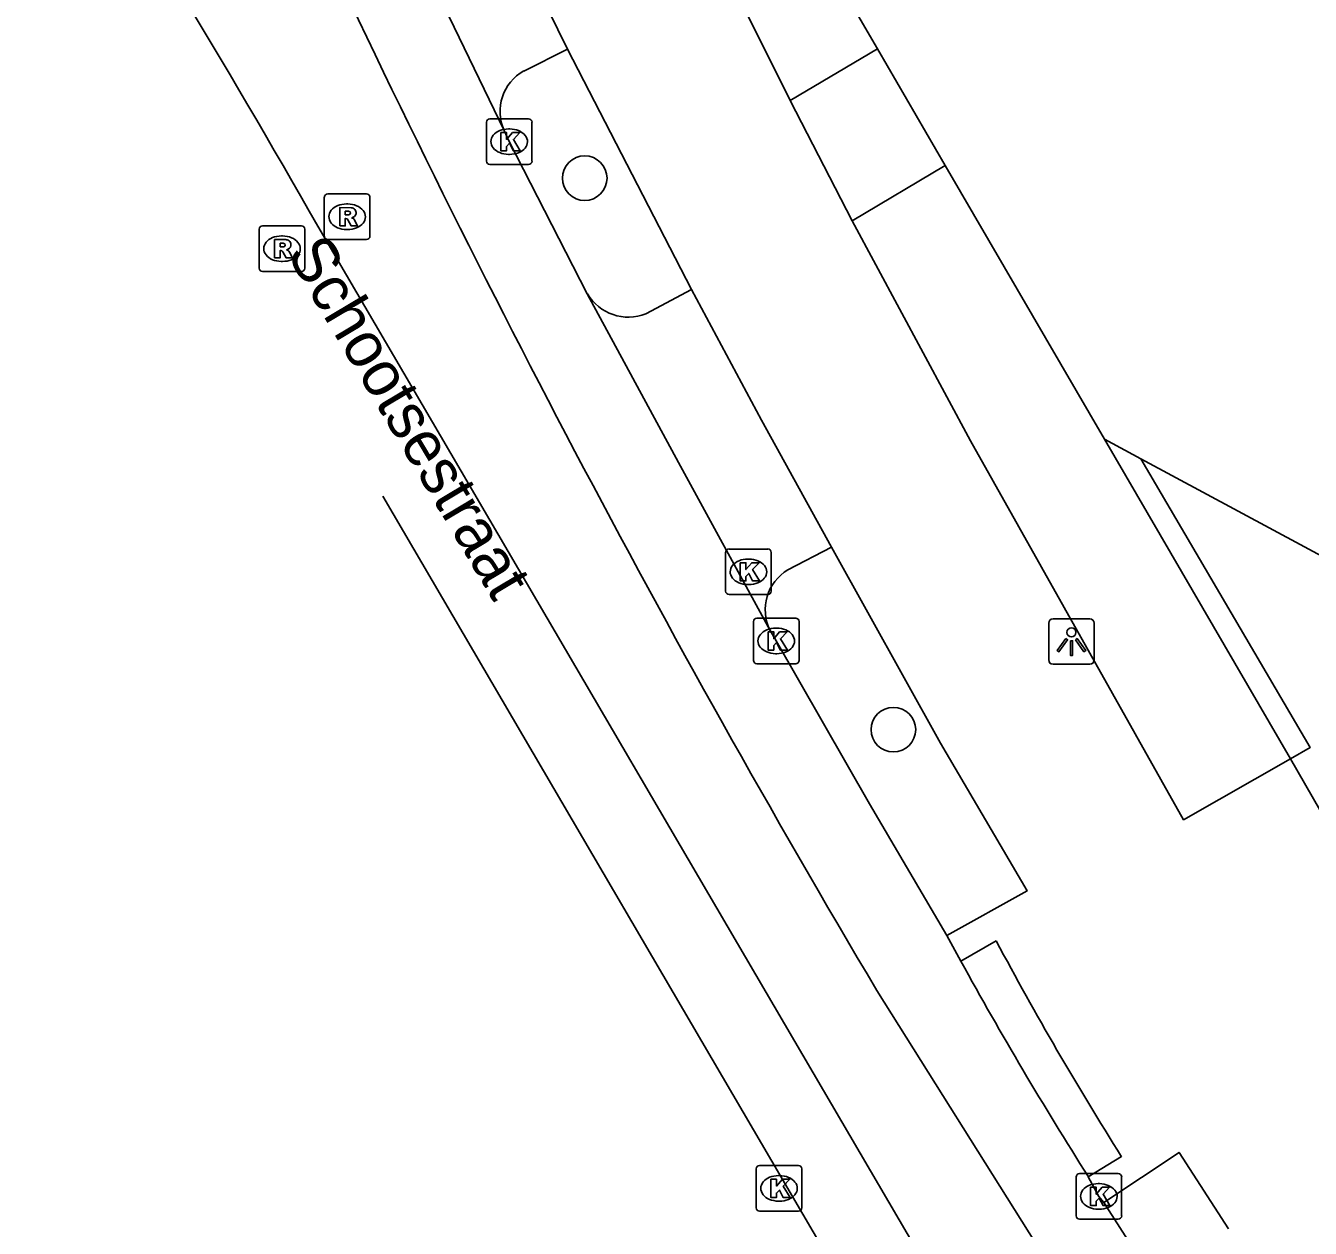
# Model space of a CAD drawing. Extents: x 159489 to 160304, y 383826 to 384530.
# Drawn here: x 159503.75 to 159531.94, y 384261.57 to 384287.96 of the extents above; entities that cross this region are included whole.
import ezdxf

# ---------------------------------------------------------------- set-up
doc = ezdxf.new("R2010")
doc.units = 0
for name, color, linetype in [('IMGEO_Boom', 7, 'Continuous'), ('IMGEO_Groenvoorziening', 7, 'Continuous'), ('IMGEO_Kolk', 7, 'Continuous'), ('IMGEO_Lichtpunt', 7, 'Continuous'), ('IMGEO_Openbare_ruimte_label', 7, 'Continuous'), ('IMGEO_Pand', 7, 'Continuous'), ('IMGEO_Parkeervlak_open', 7, 'Continuous'), ('IMGEO_Rijbaan_lokaal_gesloten', 7, 'Continuous'), ('IMGEO_Rioolput', 7, 'Continuous'), ('IMGEO_Voetpad_open', 7, 'Continuous')]:
    doc.layers.add(name, color=color, linetype=linetype)

msp = doc.modelspace()

# ---------------------------------------------------------------- linework, layer by layer
at = {"layer": 'IMGEO_Boom'}
for centre in [(159516.018, 384284.612), (159522.79, 384272.513)]:
    msp.add_circle(centre, 0.489, dxfattribs=at)
at = {"layer": 'IMGEO_Groenvoorziening'}
for points in [[(159527.419, 384278.887), (159531.499, 384271.869)], [(159528.221, 384278.456), (159531.931, 384272.12), (159531.499, 384271.869)]]:
    msp.add_lwpolyline(points, dxfattribs=at)
at = {"layer": 'IMGEO_Kolk'}
for p, q in [((159513.86, 384284.987), (159513.86, 384285.839)), ((159513.935, 384285.913), (159514.787, 384285.913)), ((159514.348, 384285.693), (159514.373, 384285.693)), ((159514.861, 384285.839), (159514.861, 384284.987)), ((159514.371, 384285.133), (159514.346, 384285.133)), ((159514.787, 384284.913), (159513.935, 384284.913)), ((159519.109, 384275.55), (159519.109, 384276.402)), ((159519.184, 384276.476), (159520.036, 384276.476)), ((159520.11, 384276.402), (159520.11, 384275.55)), ((159519.597, 384276.256), (159519.622, 384276.256)), ((159519.62, 384275.696), (159519.595, 384275.696)), ((159520.036, 384275.476), (159519.184, 384275.476)), ((159519.794, 384274.959), (159520.646, 384274.959)), ((159519.719, 384274.033), (159519.719, 384274.885)), ((159520.207, 384274.739), (159520.232, 384274.739)), ((159520.72, 384274.885), (159520.72, 384274.033)), ((159520.23, 384274.179), (159520.205, 384274.179)), ((159520.646, 384273.959), (159519.794, 384273.959)), ((159519.78, 384262.022), (159519.78, 384262.874)), ((159519.855, 384262.948), (159520.707, 384262.948)), ((159520.781, 384262.874), (159520.781, 384262.022)), ((159520.268, 384262.728), (159520.293, 384262.728)), ((159526.796, 384261.846), (159526.796, 384262.698)), ((159526.871, 384262.772), (159527.723, 384262.772)), ((159527.284, 384262.552), (159527.309, 384262.552)), ((159527.797, 384262.698), (159527.797, 384261.846)), ((159520.291, 384262.168), (159520.266, 384262.168)), ((159527.307, 384261.992), (159527.282, 384261.992)), ((159520.707, 384261.948), (159519.855, 384261.948)), ((159527.723, 384261.772), (159526.871, 384261.772))]:
    msp.add_line(p, q, dxfattribs=at)
for points in [[(159513.86, 384284.987), (159513.86, 384285.839)], [(159513.935, 384285.913), (159514.787, 384285.913)], [(159514.861, 384285.839), (159514.861, 384284.987)], [(159514.181, 384285.613), (159514.304, 384285.613), (159514.304, 384285.462), (159514.434, 384285.613), (159514.598, 384285.613), (159514.452, 384285.462), (159514.605, 384285.213), (159514.453, 384285.213), (159514.368, 384285.377), (159514.304, 384285.31), (159514.304, 384285.213), (159514.181, 384285.213), (159514.181, 384285.613)], [(159514.787, 384284.913), (159513.935, 384284.913)], [(159519.109, 384275.55), (159519.109, 384276.402)], [(159519.184, 384276.476), (159520.036, 384276.476)], [(159520.11, 384276.402), (159520.11, 384275.55)], [(159519.43, 384276.176), (159519.553, 384276.176), (159519.553, 384276.025), (159519.683, 384276.176), (159519.847, 384276.176), (159519.701, 384276.025), (159519.854, 384275.776), (159519.702, 384275.776), (159519.617, 384275.94), (159519.553, 384275.873), (159519.553, 384275.776), (159519.43, 384275.776), (159519.43, 384276.176)], [(159520.036, 384275.476), (159519.184, 384275.476)], [(159519.794, 384274.959), (159520.646, 384274.959)], [(159519.719, 384274.033), (159519.719, 384274.885)], [(159520.04, 384274.659), (159520.163, 384274.659), (159520.163, 384274.508), (159520.293, 384274.659), (159520.457, 384274.659), (159520.311, 384274.508), (159520.464, 384274.259), (159520.312, 384274.259), (159520.227, 384274.423), (159520.163, 384274.356), (159520.163, 384274.259), (159520.04, 384274.259), (159520.04, 384274.659)], [(159520.72, 384274.885), (159520.72, 384274.033)], [(159520.646, 384273.959), (159519.794, 384273.959)], [(159519.78, 384262.022), (159519.78, 384262.874)], [(159519.855, 384262.948), (159520.707, 384262.948)], [(159520.781, 384262.874), (159520.781, 384262.022)], [(159520.101, 384262.648), (159520.224, 384262.648), (159520.224, 384262.497), (159520.354, 384262.648), (159520.518, 384262.648), (159520.372, 384262.497), (159520.525, 384262.248), (159520.373, 384262.248), (159520.288, 384262.412), (159520.224, 384262.345), (159520.224, 384262.248), (159520.101, 384262.248), (159520.101, 384262.648)], [(159526.796, 384261.846), (159526.796, 384262.698)], [(159526.871, 384262.772), (159527.723, 384262.772)], [(159527.797, 384262.698), (159527.797, 384261.846)], [(159527.117, 384262.472), (159527.24, 384262.472), (159527.24, 384262.321), (159527.37, 384262.472), (159527.534, 384262.472), (159527.388, 384262.321), (159527.541, 384262.072), (159527.389, 384262.072), (159527.304, 384262.236), (159527.24, 384262.169), (159527.24, 384262.072), (159527.117, 384262.072), (159527.117, 384262.472)], [(159520.707, 384261.948), (159519.855, 384261.948)], [(159527.723, 384261.772), (159526.871, 384261.772)]]:
    msp.add_lwpolyline(points, dxfattribs=at)
for centre, start, end in [((159513.937, 384285.837), 91.552, 178.448), ((159513.937, 384285.837), 91.552, 178.448), ((159514.785, 384285.837), 1.552, 88.448), ((159514.785, 384285.837), 1.552, 88.448), ((159513.937, 384284.989), 181.552, 268.448), ((159513.937, 384284.989), 181.552, 268.448), ((159514.785, 384284.989), 271.552, 358.448), ((159514.785, 384284.989), 271.552, 358.448), ((159519.186, 384276.4), 91.552, 178.448), ((159519.186, 384276.4), 91.552, 178.448), ((159520.034, 384276.4), 1.552, 88.448), ((159520.034, 384276.4), 1.552, 88.448), ((159519.186, 384275.552), 181.552, 268.448), ((159519.186, 384275.552), 181.552, 268.448), ((159520.034, 384275.552), 271.552, 358.448), ((159520.034, 384275.552), 271.552, 358.448), ((159519.796, 384274.883), 91.552, 178.448), ((159519.796, 384274.883), 91.552, 178.448), ((159520.644, 384274.883), 1.552, 88.448), ((159520.644, 384274.883), 1.552, 88.448), ((159519.796, 384274.035), 181.552, 268.448), ((159519.796, 384274.035), 181.552, 268.448), ((159520.644, 384274.035), 271.552, 358.448), ((159520.644, 384274.035), 271.552, 358.448), ((159519.857, 384262.872), 91.552, 178.448), ((159519.857, 384262.872), 91.552, 178.448), ((159520.705, 384262.872), 1.552, 88.448), ((159520.705, 384262.872), 1.552, 88.448), ((159526.873, 384262.696), 91.552, 178.448), ((159526.873, 384262.696), 91.552, 178.448), ((159527.721, 384262.696), 1.552, 88.448), ((159527.721, 384262.696), 1.552, 88.448), ((159519.857, 384262.024), 181.552, 268.448), ((159519.857, 384262.024), 181.552, 268.448), ((159520.705, 384262.024), 271.552, 358.448), ((159520.705, 384262.024), 271.552, 358.448), ((159526.873, 384261.848), 181.552, 268.448), ((159526.873, 384261.848), 181.552, 268.448), ((159527.721, 384261.848), 271.552, 358.448), ((159527.721, 384261.848), 271.552, 358.448)]:
    msp.add_arc(centre, 0.0765, start, end, dxfattribs=at)
for centre, major_axis, ratio, start_param, end_param in [((159514.347, 384285.413), (-0.387, 0.002), 0.722429, 4.712389, 7.853982), ((159514.372, 384285.413), (-0.39, 0.002), 0.717154, 1.570796, 4.712389), ((159519.596, 384275.976), (-0.387, 0.002), 0.722429, 4.712389, 7.853982), ((159519.621, 384275.976), (-0.39, 0.002), 0.717154, 1.570796, 4.712389), ((159520.206, 384274.459), (-0.387, 0.002), 0.722429, 4.712389, 7.853982), ((159520.231, 384274.459), (-0.39, 0.002), 0.717154, 1.570796, 4.712389), ((159520.267, 384262.448), (-0.387, 0.002), 0.722429, 4.712389, 7.853982), ((159520.292, 384262.448), (-0.39, 0.002), 0.717154, 1.570796, 4.712389), ((159527.283, 384262.272), (-0.387, 0.002), 0.722429, 4.712389, 7.853982), ((159527.308, 384262.272), (-0.39, 0.002), 0.717154, 1.570796, 4.712389)]:
    msp.add_ellipse(centre, major_axis=major_axis, ratio=ratio, start_param=start_param, end_param=end_param, dxfattribs=at)
at = {"layer": 'IMGEO_Lichtpunt'}
for p, q in [((159527.099, 384274.943), (159526.291, 384274.943)), ((159527.099, 384274.943), (159526.291, 384274.943)), ((159526.197, 384274.848), (159526.197, 384274.041)), ((159526.197, 384274.848), (159526.197, 384274.041)), ((159527.193, 384274.041), (159527.193, 384274.848)), ((159527.193, 384274.041), (159527.193, 384274.848)), ((159526.291, 384273.947), (159527.099, 384273.947)), ((159526.291, 384273.947), (159527.099, 384273.947))]:
    msp.add_line(p, q, dxfattribs=at)
for points in [[(159526.571, 384274.512), (159526.61, 384274.484), (159526.422, 384274.222), (159526.384, 384274.249), (159526.571, 384274.512)], [(159526.673, 384274.464), (159526.72, 384274.464), (159526.72, 384274.142), (159526.673, 384274.142), (159526.673, 384274.464)], [(159526.783, 384274.484), (159526.821, 384274.511), (159527.008, 384274.249), (159526.969, 384274.221), (159526.783, 384274.484)]]:
    msp.add_lwpolyline(points, dxfattribs=at)
msp.add_circle((159526.696, 384274.646), 0.0994, dxfattribs=at)
for centre, start, end in [((159526.291, 384274.848), 90, 180), ((159526.291, 384274.848), 90, 180), ((159527.099, 384274.848), 0, 90), ((159527.099, 384274.848), 0, 90), ((159526.291, 384274.041), 180, 270), ((159526.291, 384274.041), 180, 270), ((159527.099, 384274.041), 270, 0), ((159527.099, 384274.041), 270, 360)]:
    msp.add_arc(centre, 0.0946, start, end, dxfattribs=at)
at = {"layer": 'IMGEO_Pand'}
for points in [[(159522.438, 384287.447), (159519.377, 384292.707)], [(159523.926, 384284.889), (159522.438, 384287.447)], [(159527.419, 384278.887), (159523.926, 384284.889)], [(159528.221, 384278.456), (159527.419, 384278.887)], [(159541.03, 384271.564), (159528.221, 384278.456)]]:
    msp.add_lwpolyline(points, dxfattribs=at)
at = {"layer": 'IMGEO_Parkeervlak_open'}
for points in [[(159514.684, 384286.963), (159515.642, 384287.44)], [(159518.362, 384282.168), (159517.361, 384281.633)], [(159520.477, 384276.021), (159521.428, 384276.516)]]:
    msp.add_lwpolyline(points, dxfattribs=at)
for centre, radius, start, end in [((159515.17, 384286.077), 1.011, 118.7446, 204.3328), ((159516.982, 384282.622), 1.059, 211.153, 290.9908), ((159521, 384275.144), 1.021, 120.7997, 206.3559)]:
    msp.add_arc(centre, radius, start, end, dxfattribs=at)
at = {"layer": 'IMGEO_Rijbaan_lokaal_gesloten'}
for points in [[(159510.503, 384293.281), (159512.388, 384289.519), (159514.249, 384285.66)], [(159514.249, 384285.66), (159514.361, 384285.413), (159516.075, 384282.074)], [(159510.16, 384283.557), (159523.948, 384259.997)], [(159516.075, 384282.074), (159518.077, 384278.372), (159520.085, 384274.691)], [(159522.115, 384259.647), (159511.588, 384277.632)], [(159520.085, 384274.691), (159520.22, 384274.459), (159522.265, 384270.887), (159523.961, 384267.993)], [(159523.961, 384267.993), (159524.271, 384267.433)], [(159525.931, 384261.215), (159522.428, 384266.788)], [(159527.066, 384262.703), (159527.297, 384262.272), (159527.408, 384262.135)], [(159527.408, 384262.135), (159528.457, 384260.496)]]:
    msp.add_lwpolyline(points, dxfattribs=at)
for centre, radius, start, end in [((159356.003, 384196.45), 177.065, 29.46867, 33.44179), ((159750.363, 384402.196), 265.122, 204.852, 210.71312), ((159600.837, 384309.485), 87.354, 208.77713, 212.38132)]:
    msp.add_arc(centre, radius, start, end, dxfattribs=at)
at = {"layer": 'IMGEO_Rioolput'}
for p, q in [((159510.38, 384284.266), (159511.232, 384284.266)), ((159510.305, 384283.34), (159510.305, 384284.192)), ((159510.793, 384284.046), (159510.818, 384284.046)), ((159511.306, 384284.192), (159511.306, 384283.34)), ((159508.876, 384282.639), (159508.876, 384283.491)), ((159508.951, 384283.565), (159509.803, 384283.565)), ((159509.877, 384283.491), (159509.877, 384282.639)), ((159510.816, 384283.486), (159510.791, 384283.486)), ((159509.364, 384283.345), (159509.389, 384283.345)), ((159511.232, 384283.266), (159510.38, 384283.266)), ((159509.803, 384282.565), (159508.951, 384282.565)), ((159509.387, 384282.785), (159509.362, 384282.785))]:
    msp.add_line(p, q, dxfattribs=at)
for points in [[(159510.38, 384284.266), (159511.232, 384284.266)], [(159510.305, 384283.34), (159510.305, 384284.192)], [(159510.894, 384283.964), (159510.642, 384283.966), (159510.642, 384283.566)], [(159511.306, 384284.192), (159511.306, 384283.34)], [(159510.642, 384283.566), (159510.766, 384283.566), (159510.766, 384283.728), (159510.777, 384283.728)], [(159510.82, 384283.885), (159510.766, 384283.885), (159510.766, 384283.804)], [(159510.766, 384283.804), (159510.818, 384283.804)], [(159510.824, 384283.699), (159510.895, 384283.566), (159511.035, 384283.566), (159510.97, 384283.692)], [(159508.876, 384282.639), (159508.876, 384283.491)], [(159508.951, 384283.565), (159509.803, 384283.565)], [(159509.877, 384283.491), (159509.877, 384282.639)], [(159509.465, 384283.263), (159509.213, 384283.265), (159509.213, 384282.865)], [(159509.391, 384283.184), (159509.337, 384283.184), (159509.337, 384283.103)], [(159511.232, 384283.266), (159510.38, 384283.266)], [(159509.213, 384282.865), (159509.337, 384282.865), (159509.337, 384283.027), (159509.348, 384283.027)], [(159509.337, 384283.103), (159509.389, 384283.103)], [(159509.395, 384282.998), (159509.466, 384282.865), (159509.606, 384282.865), (159509.541, 384282.991)], [(159509.803, 384282.565), (159508.951, 384282.565)]]:
    msp.add_lwpolyline(points, dxfattribs=at)
for centre, radius, start, end in [((159510.382, 384284.19), 0.0765, 91.552, 178.448), ((159510.382, 384284.19), 0.0765, 91.552, 178.448), ((159511.23, 384284.19), 0.0765, 1.552, 88.448), ((159511.23, 384284.19), 0.0765, 1.552, 88.448), ((159510.893, 384283.854), 0.109, 350.3612, 89.416), ((159510.776, 384283.675), 0.0533, 26.0293, 88.6989), ((159510.802, 384283.993), 0.19, 274.7715, 282.9687), ((159510.826, 384283.789), 0.0964, 77.0061, 93.1865), ((159510.84, 384283.846), 0.0378, 276.6634, 79.6772), ((159510.891, 384283.854), 0.112, 277.5842, 350.9817), ((159510.875, 384283.639), 0.108, 29.5134, 73.7905), ((159508.953, 384283.489), 0.0765, 91.552, 178.448), ((159508.953, 384283.489), 0.0765, 91.552, 178.448), ((159509.801, 384283.489), 0.0765, 1.552, 88.448), ((159509.801, 384283.489), 0.0765, 1.552, 88.448), ((159509.373, 384283.292), 0.19, 274.7715, 282.9687), ((159509.397, 384283.088), 0.0964, 77.0061, 93.1865), ((159509.411, 384283.145), 0.0378, 276.6634, 79.6772), ((159509.464, 384283.153), 0.109, 350.3612, 89.416), ((159509.462, 384283.153), 0.112, 277.5842, 350.9817), ((159510.382, 384283.342), 0.0765, 181.552, 268.448), ((159510.382, 384283.342), 0.0765, 181.552, 268.448), ((159511.23, 384283.342), 0.0765, 271.552, 358.448), ((159511.23, 384283.342), 0.0765, 271.552, 358.448), ((159509.347, 384282.974), 0.0533, 26.0293, 88.6989), ((159509.446, 384282.938), 0.108, 29.5134, 73.7905), ((159508.953, 384282.641), 0.0765, 181.552, 268.448), ((159508.953, 384282.641), 0.0765, 181.552, 268.448), ((159509.801, 384282.641), 0.0765, 271.552, 358.448), ((159509.801, 384282.641), 0.0765, 271.552, 358.448)]:
    msp.add_arc(centre, radius, start, end, dxfattribs=at)
for centre, major_axis, ratio, start_param, end_param in [((159510.792, 384283.766), (-0.387, 0.002), 0.722429, 4.712389, 7.853982), ((159510.817, 384283.766), (-0.39, 0.002), 0.717154, 1.570796, 4.712389), ((159509.363, 384283.065), (-0.387, 0.002), 0.722429, 4.712389, 7.853982), ((159509.388, 384283.065), (-0.39, 0.002), 0.717154, 1.570796, 4.712389)]:
    msp.add_ellipse(centre, major_axis=major_axis, ratio=ratio, start_param=start_param, end_param=end_param, dxfattribs=at)
at = {"layer": 'IMGEO_Voetpad_open'}
for points in [[(159516.4, 384294.599), (159520.528, 384286.319)], [(159515.642, 384287.44), (159514.162, 384290.453), (159512.841, 384293.275)], [(159518.362, 384282.168), (159515.642, 384287.44)], [(159520.528, 384286.319), (159522.438, 384287.447)], [(159520.528, 384286.319), (159521.885, 384283.676)], [(159523.926, 384284.889), (159521.885, 384283.676)], [(159521.885, 384283.676), (159524.479, 384278.85), (159529.156, 384270.537), (159531.499, 384271.869)], [(159521.428, 384276.516), (159519.898, 384279.303), (159518.362, 384282.168)], [(159523.961, 384267.993), (159525.723, 384268.974), (159523.825, 384272.217), (159521.428, 384276.516)], [(159531.499, 384271.869), (159534.333, 384266.954)], [(159525.047, 384267.876), (159524.271, 384267.433)], [(159527.066, 384262.703), (159527.795, 384263.144)], [(159530.14, 384261.558), (159529.056, 384263.238), (159527.408, 384262.135)]]:
    msp.add_lwpolyline(points, dxfattribs=at)
msp.add_arc((159589.415, 384302.092), 72.897, 207.99392, 212.29586, dxfattribs=at)

# ---------------------------------------------------------------- texts
at = {"layer": 'IMGEO_Openbare_ruimte_label'}
msp.add_text('Schootsestraat', height=1, rotation=300.7967, dxfattribs=at).set_placement((159509.465, 384282.956))

doc.saveas('drawing.dxf')
